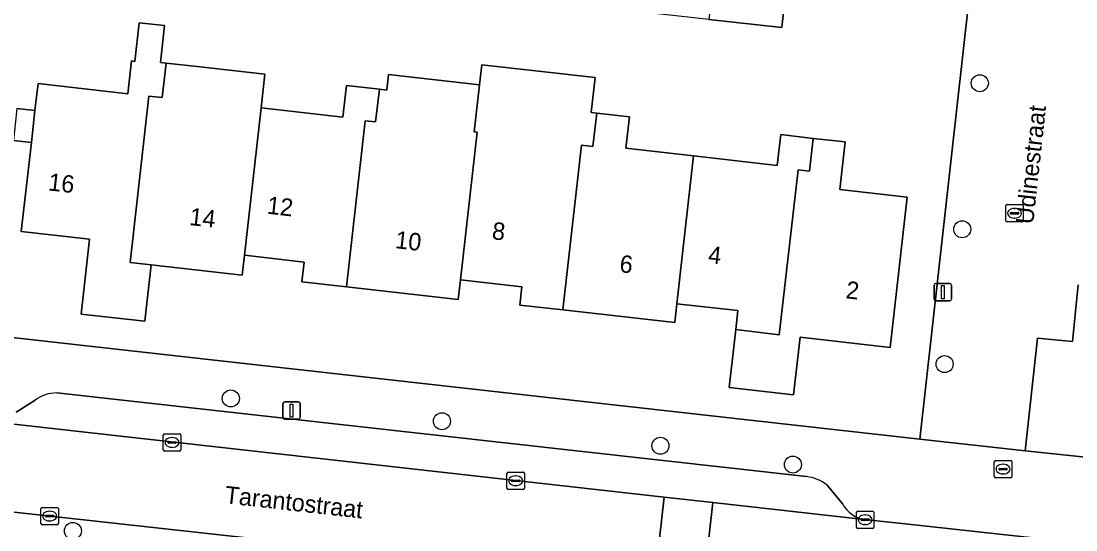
# Model space of a CAD drawing. Extents: x 162082 to 163401, y 388089 to 388636.
# Drawn here: x 162786.3 to 162846.8, y 388208.4 to 388237.6 of the extents above; entities that cross this region are included whole.
import ezdxf

# ---------------------------------------------------------------- set-up
doc = ezdxf.new("R2010")
doc.units = 0
for name, color, linetype in [('IMGEO_Boom', 7, 'Continuous'), ('IMGEO_Brandkraan', 7, 'Continuous'), ('IMGEO_Erf', 7, 'Continuous'), ('IMGEO_Kolk', 7, 'Continuous'), ('IMGEO_Lichtmast', 7, 'Continuous'), ('IMGEO_Openbare_ruimte_label', 7, 'Continuous'), ('IMGEO_Pand', 7, 'Continuous'), ('IMGEO_Pand_nummerreeks', 7, 'Continuous'), ('IMGEO_Parkeervlak_open', 7, 'Continuous'), ('IMGEO_Rijbaan_lokaal_open', 7, 'Continuous'), ('IMGEO_Voetpad_open', 7, 'Continuous')]:
    doc.layers.add(name, color=color, linetype=linetype)

msp = doc.modelspace()

# ---------------------------------------------------------------- linework, layer by layer
at = {"layer": 'IMGEO_Boom'}
for centre in [(162841.322, 388234.002), (162840.312, 388225.617), (162839.302, 388217.879), (162798.306, 388215.904), (162810.433, 388214.596), (162822.978, 388213.187), (162830.586, 388212.107), (162789.234, 388208.298)]:
    msp.add_circle(centre, 0.489, dxfattribs=at)
at = {"layer": 'IMGEO_Brandkraan'}
for p, q in [((162842.154, 388211.422), (162842.154, 388212.274)), ((162842.229, 388212.348), (162843.081, 388212.348)), ((162843.155, 388212.274), (162843.155, 388211.422)), ((162842.413, 388211.842), (162842.413, 388211.854)), ((162842.851, 388211.805), (162842.453, 388211.805)), ((162842.456, 388211.891), (162842.854, 388211.891)), ((162842.642, 388212.128), (162842.667, 388212.128)), ((162842.897, 388211.854), (162842.897, 388211.842)), ((162843.081, 388211.348), (162842.229, 388211.348)), ((162842.665, 388211.568), (162842.64, 388211.568))]:
    msp.add_line(p, q, dxfattribs=at)
for points in [[(162842.154, 388211.422), (162842.154, 388212.274)], [(162842.229, 388212.348), (162843.081, 388212.348)], [(162843.155, 388212.274), (162843.155, 388211.422)], [(162843.081, 388211.348), (162842.229, 388211.348)]]:
    msp.add_lwpolyline(points, dxfattribs=at)
for centre, radius, start, end in [((162842.231, 388212.272), 0.0765, 91.55205, 178.44795), ((162842.231, 388212.272), 0.0765, 91.55205, 178.44795), ((162843.079, 388212.272), 0.0765, 1.55205, 88.44795), ((162843.079, 388212.272), 0.0765, 1.55205, 88.44795), ((162842.453, 388211.851), 0.0403, 85.87752, 175.75265), ((162842.45, 388211.841), 0.0366, 178.93798, 274.71019), ((162842.854, 388211.848), 0.043, 264.86636, 352.45326), ((162842.858, 388211.853), 0.0386, 1.73085, 96.63898), ((162842.231, 388211.424), 0.0765, 181.55205, 268.44795), ((162842.231, 388211.424), 0.0765, 181.55205, 268.44795), ((162843.079, 388211.424), 0.0765, 271.55205, 358.44795), ((162843.079, 388211.424), 0.0765, 271.55205, 358.44795)]:
    msp.add_arc(centre, radius, start, end, dxfattribs=at)
for centre, major_axis, ratio, start_param, end_param in [((162842.641, 388211.848), (-0.387, 0.002), 0.722429, 4.712389, 7.853982), ((162842.666, 388211.848), (-0.39, 0.002), 0.717154, 1.570796, 4.712389)]:
    msp.add_ellipse(centre, major_axis=major_axis, ratio=ratio, start_param=start_param, end_param=end_param, dxfattribs=at)
at = {"layer": 'IMGEO_Erf'}
msp.add_lwpolyline([(162821.433, 388238.137), (162821.739, 388240.934), (162818.357, 388241.345), (162818.041, 388238.547), (162813.346, 388239.079), (162808.513, 388239.648), (162808.844, 388242.48), (162805.899, 388242.824), (162805.568, 388239.992), (162800.951, 388240.532), (162796.218, 388241.085), (162796.532, 388243.772), (162786.323, 388244.931), (162783.503, 388219.652), (162837.876, 388213.576), (162840.707, 388238.931), (162830.248, 388240.007), (162829.943, 388237.21), (162825.765, 388237.665)], close=True, dxfattribs=at)
for points in [[(162786.024, 388232.558), (162787.059, 388232.441), (162787.233, 388233.982), (162792.383, 388233.4), (162792.596, 388235.283), (162792.788, 388235.261), (162793.038, 388237.477), (162794.503, 388237.312), (162794.264, 388235.194), (162794.584, 388235.158), (162796.376, 388234.956), (162800.268, 388234.517), (162800.048, 388232.583), (162804.735, 388232.053), (162804.941, 388233.874), (162806.836, 388233.66), (162807.258, 388233.612), (162807.358, 388234.498), (162812.591, 388233.907), (162812.722, 388235.067), (162819.238, 388234.331), (162819.009, 388232.322), (162819.317, 388232.287), (162821.2, 388232.074), (162820.996, 388230.268), (162824.879, 388229.829), (162829.686, 388229.286), (162829.886, 388231.051), (162831.76, 388230.839), (162833.584, 388230.633), (162833.275, 388227.895), (162837.145, 388227.458), (162836.17, 388218.832), (162831.001, 388219.416), (162830.627, 388216.109), (162826.929, 388216.527), (162827.307, 388219.868), (162827.429, 388220.947), (162823.919, 388221.343), (162823.797, 388220.264), (162817.38, 388220.988), (162814.895, 388221.269), (162815.014, 388222.319), (162811.495, 388222.716), (162811.367, 388221.589), (162804.945, 388222.314), (162802.381, 388222.604), (162802.509, 388223.738), (162799.087, 388224.125), (162798.958, 388222.984), (162793.729, 388223.574), (162793.363, 388220.336), (162789.706, 388220.749), (162790.192, 388225.048), (162786.274, 388225.49), (162786.851, 388230.597), (162785.815, 388230.714)], [(162846.974, 388222.431), (162846.648, 388219.169), (162844.643, 388219.359), (162843.932, 388212.902), (162869.062, 388210.255)]]:
    msp.add_lwpolyline(points, dxfattribs=at)
at = {"layer": 'IMGEO_Kolk'}
for p, q in [((162842.813, 388226.112), (162842.813, 388226.964)), ((162842.888, 388227.038), (162843.74, 388227.038)), ((162843.301, 388226.818), (162843.326, 388226.818)), ((162843.814, 388226.964), (162843.814, 388226.112)), ((162843.072, 388226.532), (162843.072, 388226.544)), ((162843.51, 388226.495), (162843.112, 388226.495)), ((162843.115, 388226.581), (162843.513, 388226.581)), ((162843.324, 388226.258), (162843.299, 388226.258)), ((162843.556, 388226.544), (162843.556, 388226.532)), ((162843.74, 388226.038), (162842.888, 388226.038)), ((162794.427, 388212.952), (162794.427, 388213.804)), ((162794.502, 388213.878), (162795.354, 388213.878)), ((162794.915, 388213.658), (162794.94, 388213.658)), ((162795.428, 388213.804), (162795.428, 388212.952)), ((162795.354, 388212.878), (162794.502, 388212.878)), ((162794.686, 388213.372), (162794.686, 388213.384)), ((162795.124, 388213.335), (162794.726, 388213.335)), ((162794.729, 388213.421), (162795.127, 388213.421)), ((162794.938, 388213.098), (162794.913, 388213.098)), ((162795.17, 388213.384), (162795.17, 388213.372)), ((162814.24, 388211.679), (162815.092, 388211.679)), ((162814.165, 388210.753), (162814.165, 388211.605)), ((162814.424, 388211.173), (162814.424, 388211.185)), ((162814.862, 388211.136), (162814.464, 388211.136)), ((162814.467, 388211.222), (162814.865, 388211.222)), ((162814.653, 388211.459), (162814.678, 388211.459)), ((162814.908, 388211.185), (162814.908, 388211.173)), ((162815.166, 388211.605), (162815.166, 388210.753)), ((162815.092, 388210.679), (162814.24, 388210.679)), ((162814.676, 388210.899), (162814.651, 388210.899)), ((162787.401, 388208.726), (162787.401, 388209.578)), ((162787.476, 388209.652), (162788.328, 388209.652)), ((162787.703, 388209.195), (162788.101, 388209.195)), ((162787.889, 388209.432), (162787.914, 388209.432)), ((162788.402, 388209.578), (162788.402, 388208.726)), ((162834.239, 388208.515), (162834.239, 388209.367)), ((162834.314, 388209.441), (162835.166, 388209.441)), ((162834.727, 388209.221), (162834.752, 388209.221)), ((162835.24, 388209.367), (162835.24, 388208.515)), ((162788.328, 388208.652), (162787.476, 388208.652)), ((162787.66, 388209.146), (162787.66, 388209.158)), ((162788.098, 388209.109), (162787.7, 388209.109)), ((162787.912, 388208.872), (162787.887, 388208.872)), ((162788.144, 388209.158), (162788.144, 388209.146)), ((162834.498, 388208.935), (162834.498, 388208.947)), ((162834.936, 388208.898), (162834.538, 388208.898)), ((162834.541, 388208.984), (162834.939, 388208.984)), ((162834.75, 388208.661), (162834.725, 388208.661)), ((162834.982, 388208.947), (162834.982, 388208.935)), ((162835.166, 388208.441), (162834.314, 388208.441))]:
    msp.add_line(p, q, dxfattribs=at)
for points in [[(162842.813, 388226.112), (162842.813, 388226.964)], [(162842.888, 388227.038), (162843.74, 388227.038)], [(162843.814, 388226.964), (162843.814, 388226.112)], [(162843.74, 388226.038), (162842.888, 388226.038)], [(162794.427, 388212.952), (162794.427, 388213.804)], [(162794.502, 388213.878), (162795.354, 388213.878)], [(162795.428, 388213.804), (162795.428, 388212.952)], [(162795.354, 388212.878), (162794.502, 388212.878)], [(162814.24, 388211.679), (162815.092, 388211.679)], [(162814.165, 388210.753), (162814.165, 388211.605)], [(162815.166, 388211.605), (162815.166, 388210.753)], [(162815.092, 388210.679), (162814.24, 388210.679)], [(162787.401, 388208.726), (162787.401, 388209.578)], [(162787.476, 388209.652), (162788.328, 388209.652)], [(162788.402, 388209.578), (162788.402, 388208.726)], [(162834.239, 388208.515), (162834.239, 388209.367)], [(162834.314, 388209.441), (162835.166, 388209.441)], [(162835.24, 388209.367), (162835.24, 388208.515)], [(162788.328, 388208.652), (162787.476, 388208.652)], [(162835.166, 388208.441), (162834.314, 388208.441)]]:
    msp.add_lwpolyline(points, dxfattribs=at)
for centre, radius, start, end in [((162842.89, 388226.962), 0.0765, 91.55205, 178.44795), ((162842.89, 388226.962), 0.0765, 91.55205, 178.44795), ((162843.738, 388226.962), 0.0765, 1.55205, 88.44795), ((162843.738, 388226.962), 0.0765, 1.55205, 88.44795), ((162843.112, 388226.541), 0.0403, 85.87752, 175.75265), ((162843.109, 388226.531), 0.0366, 178.93798, 274.71019), ((162843.513, 388226.538), 0.043, 264.86636, 352.45326), ((162843.517, 388226.543), 0.0386, 1.73085, 96.63898), ((162842.89, 388226.114), 0.0765, 181.55205, 268.44795), ((162842.89, 388226.114), 0.0765, 181.55205, 268.44795), ((162843.738, 388226.114), 0.0765, 271.55205, 358.44795), ((162843.738, 388226.114), 0.0765, 271.55205, 358.44795), ((162794.504, 388213.802), 0.0765, 91.55205, 178.44795), ((162794.504, 388213.802), 0.0765, 91.55205, 178.44795), ((162795.352, 388213.802), 0.0765, 1.55205, 88.44795), ((162795.352, 388213.802), 0.0765, 1.55205, 88.44795), ((162794.504, 388212.954), 0.0765, 181.55205, 268.44795), ((162794.504, 388212.954), 0.0765, 181.55205, 268.44795), ((162794.726, 388213.381), 0.0403, 85.87752, 175.75265), ((162794.723, 388213.371), 0.0366, 178.93798, 274.71019), ((162795.127, 388213.378), 0.043, 264.86636, 352.45326), ((162795.131, 388213.383), 0.0386, 1.73085, 96.63898), ((162795.352, 388212.954), 0.0765, 271.55205, 358.44795), ((162795.352, 388212.954), 0.0765, 271.55205, 358.44795), ((162814.242, 388211.603), 0.0765, 91.55205, 178.44795), ((162814.242, 388211.603), 0.0765, 91.55205, 178.44795), ((162815.09, 388211.603), 0.0765, 1.55205, 88.44795), ((162815.09, 388211.603), 0.0765, 1.55205, 88.44795), ((162814.464, 388211.182), 0.0403, 85.87752, 175.75265), ((162814.461, 388211.172), 0.0366, 178.93798, 274.71019), ((162814.865, 388211.179), 0.043, 264.86636, 352.45326), ((162814.869, 388211.184), 0.0386, 1.73085, 96.63898), ((162814.242, 388210.755), 0.0765, 181.55205, 268.44795), ((162814.242, 388210.755), 0.0765, 181.55205, 268.44795), ((162815.09, 388210.755), 0.0765, 271.55205, 358.44795), ((162815.09, 388210.755), 0.0765, 271.55205, 358.44795), ((162787.478, 388209.576), 0.0765, 91.55205, 178.44795), ((162787.478, 388209.576), 0.0765, 91.55205, 178.44795), ((162787.7, 388209.155), 0.0403, 85.87752, 175.75265), ((162788.105, 388209.157), 0.0386, 1.73085, 96.63898), ((162788.326, 388209.576), 0.0765, 1.55205, 88.44795), ((162788.326, 388209.576), 0.0765, 1.55205, 88.44795), ((162834.316, 388209.365), 0.0765, 91.55205, 178.44795), ((162834.316, 388209.365), 0.0765, 91.55205, 178.44795), ((162835.164, 388209.365), 0.0765, 1.55205, 88.44795), ((162835.164, 388209.365), 0.0765, 1.55205, 88.44795), ((162787.478, 388208.728), 0.0765, 181.55205, 268.44795), ((162787.478, 388208.728), 0.0765, 181.55205, 268.44795), ((162787.697, 388209.145), 0.0366, 178.93798, 274.71019), ((162788.101, 388209.152), 0.043, 264.86636, 352.45326), ((162788.326, 388208.728), 0.0765, 271.55205, 358.44795), ((162788.326, 388208.728), 0.0765, 271.55205, 358.44795), ((162834.538, 388208.944), 0.0403, 85.87752, 175.75265), ((162834.535, 388208.934), 0.0366, 178.93798, 274.71019), ((162834.939, 388208.941), 0.043, 264.86636, 352.45326), ((162834.943, 388208.946), 0.0386, 1.73085, 96.63898), ((162834.316, 388208.517), 0.0765, 181.55205, 268.44795), ((162834.316, 388208.517), 0.0765, 181.55205, 268.44795), ((162835.164, 388208.517), 0.0765, 271.55205, 358.44795), ((162835.164, 388208.517), 0.0765, 271.55205, 358.44795)]:
    msp.add_arc(centre, radius, start, end, dxfattribs=at)
for centre, major_axis, ratio, start_param, end_param in [((162843.3, 388226.538), (-0.387, 0.002), 0.722429, 4.712389, 7.853982), ((162843.325, 388226.538), (-0.39, 0.002), 0.717154, 1.570796, 4.712389), ((162794.914, 388213.378), (-0.387, 0.002), 0.722429, 4.712389, 7.853982), ((162794.939, 388213.378), (-0.39, 0.002), 0.717154, 1.570796, 4.712389), ((162814.652, 388211.179), (-0.387, 0.002), 0.722429, 4.712389, 7.853982), ((162814.677, 388211.179), (-0.39, 0.002), 0.717154, 1.570796, 4.712389), ((162787.888, 388209.152), (-0.387, 0.002), 0.722429, 4.712389, 7.853982), ((162787.913, 388209.152), (-0.39, 0.002), 0.717154, 1.570796, 4.712389), ((162834.726, 388208.941), (-0.387, 0.002), 0.722429, 4.712389, 7.853982), ((162834.751, 388208.941), (-0.39, 0.002), 0.717154, 1.570796, 4.712389)]:
    msp.add_ellipse(centre, major_axis=major_axis, ratio=ratio, start_param=start_param, end_param=end_param, dxfattribs=at)
at = {"layer": 'IMGEO_Lichtmast'}
for p, q in [((162838.699, 388221.607), (162838.699, 388222.407)), ((162838.699, 388222.407), (162838.699, 388221.607)), ((162838.799, 388222.507), (162839.589, 388222.507)), ((162839.589, 388222.507), (162838.799, 388222.507)), ((162839.689, 388222.407), (162839.689, 388221.607)), ((162839.689, 388221.607), (162839.689, 388222.407)), ((162839.589, 388221.507), (162838.799, 388221.507)), ((162838.799, 388221.507), (162839.589, 388221.507)), ((162801.3, 388214.808), (162801.3, 388215.608)), ((162801.3, 388215.608), (162801.3, 388214.808)), ((162801.4, 388215.708), (162802.19, 388215.708)), ((162802.19, 388215.708), (162801.4, 388215.708)), ((162802.29, 388215.608), (162802.29, 388214.808)), ((162802.29, 388214.808), (162802.29, 388215.608)), ((162802.19, 388214.708), (162801.4, 388214.708)), ((162801.4, 388214.708), (162802.19, 388214.708))]:
    msp.add_line(p, q, dxfattribs=at)
for points in [[(162839.119, 388222.382), (162839.269, 388222.382), (162839.269, 388221.632), (162839.119, 388221.632), (162839.119, 388222.382)], [(162801.72, 388215.583), (162801.87, 388215.583), (162801.87, 388214.833), (162801.72, 388214.833), (162801.72, 388215.583)]]:
    msp.add_lwpolyline(points, dxfattribs=at)
for centre, start, end in [((162838.799, 388222.407), 90, 180), ((162838.799, 388222.407), 90, 180), ((162839.589, 388222.407), 0, 90), ((162839.589, 388222.407), 360, 90), ((162838.799, 388221.607), 180, 270), ((162838.799, 388221.607), 180, 270), ((162839.589, 388221.607), 270, 0), ((162839.589, 388221.607), 270, 0), ((162801.4, 388215.608), 90, 180), ((162801.4, 388215.608), 90, 180), ((162802.19, 388215.608), 0, 90), ((162802.19, 388215.608), 360, 90), ((162801.4, 388214.808), 180, 270), ((162801.4, 388214.808), 180, 270), ((162802.19, 388214.808), 270, 0), ((162802.19, 388214.808), 270, 0)]:
    msp.add_arc(centre, 0.1, start, end, dxfattribs=at)
at = {"layer": 'IMGEO_Pand'}
for points in [[(162830.248, 388240.007), (162826.082, 388240.461), (162825.765, 388237.665), (162829.943, 388237.21)], [(162793.6, 388233.262), (162794.359, 388233.176), (162794.584, 388235.158), (162794.264, 388235.194), (162794.503, 388237.312), (162793.038, 388237.477), (162792.788, 388235.261), (162792.596, 388235.283), (162792.383, 388233.4), (162787.233, 388233.982), (162787.059, 388232.441), (162786.851, 388230.597), (162786.274, 388225.49), (162790.192, 388225.048), (162789.706, 388220.749), (162793.363, 388220.336), (162793.729, 388223.574), (162792.517, 388223.711)], [(162800.048, 388232.583), (162800.268, 388234.517), (162796.376, 388234.956), (162794.584, 388235.158), (162794.359, 388233.176), (162793.6, 388233.262), (162792.517, 388223.711), (162793.729, 388223.574), (162798.958, 388222.984), (162799.087, 388224.125)], [(162818.452, 388230.444), (162819.099, 388230.37), (162819.317, 388232.287), (162819.009, 388232.322), (162819.238, 388234.331), (162812.722, 388235.067), (162812.591, 388233.907), (162812.287, 388231.213), (162812.454, 388231.194), (162811.495, 388222.716), (162815.014, 388222.319), (162814.895, 388221.269), (162817.38, 388220.988)], [(162812.454, 388231.194), (162812.287, 388231.213), (162812.591, 388233.907), (162807.358, 388234.498), (162807.258, 388233.612), (162806.836, 388233.66), (162806.623, 388231.786), (162806.026, 388231.854), (162804.945, 388222.314), (162811.367, 388221.589), (162811.495, 388222.716)], [(162804.945, 388222.314), (162806.026, 388231.854), (162806.623, 388231.786), (162806.836, 388233.66), (162804.941, 388233.874), (162804.735, 388232.053), (162800.048, 388232.583), (162799.087, 388224.125), (162802.509, 388223.738), (162802.381, 388222.604)], [(162787.059, 388232.441), (162786.024, 388232.558), (162785.815, 388230.714), (162786.851, 388230.597)], [(162819.317, 388232.287), (162819.099, 388230.37), (162818.452, 388230.444), (162817.38, 388220.988), (162823.797, 388220.264), (162823.919, 388221.343), (162824.879, 388229.829), (162820.996, 388230.268), (162821.2, 388232.074)], [(162824.879, 388229.829), (162823.919, 388221.343), (162827.429, 388220.947), (162827.307, 388219.868), (162829.804, 388219.55), (162830.88, 388229.035), (162831.547, 388228.959), (162831.76, 388230.839), (162829.886, 388231.051), (162829.686, 388229.286)], [(162831.76, 388230.839), (162831.547, 388228.959), (162830.88, 388229.035), (162829.804, 388219.55), (162827.307, 388219.868), (162826.929, 388216.527), (162830.627, 388216.109), (162831.001, 388219.416), (162836.17, 388218.832), (162837.145, 388227.458), (162833.275, 388227.895), (162833.584, 388230.633)]]:
    msp.add_lwpolyline(points, close=True, dxfattribs=at)
at = {"layer": 'IMGEO_Parkeervlak_open'}
for points in [[(162831.364, 388211.416), (162788.305, 388216.218)], [(162787.062, 388215.802), (162785.981, 388215.126)], [(162784.632, 388214.568), (162823.2, 388210.24), (162825.987, 388209.927), (162834.672, 388208.952)], [(162833.447, 388209.83), (162832.549, 388210.917)]]:
    msp.add_lwpolyline(points, dxfattribs=at)
for centre, radius, start, end in [((162788.263, 388214.278), 1.941, 88.76888, 128.23925), ((162831.168, 388209.294), 2.131, 49.60852, 84.71985), ((162835.022, 388210.734), 1.816, 209.85241, 258.88662)]:
    msp.add_arc(centre, radius, start, end, dxfattribs=at)
at = {"layer": 'IMGEO_Rijbaan_lokaal_open'}
msp.add_lwpolyline([(162847.601, 388300.888), (162845.633, 388283.31), (162845.032, 388277.944), (162844.24, 388270.888), (162843.614, 388265.311), (162841.916, 388250), (162841.425, 388245.495), (162841.16, 388243.06), (162840.876, 388240.446), (162840.868, 388240.375), (162840.707, 388238.931), (162837.876, 388213.576), (162843.932, 388212.902), (162844.643, 388219.359), (162846.648, 388219.169), (162846.974, 388222.431)], dxfattribs=at)
for points in [[(162784.632, 388214.568), (162782.28, 388214.832), (162778.534, 388215.253), (162775.49, 388215.519), (162758.442, 388217.51), (162757.897, 388212.563), (162764.696, 388211.8), (162764.85, 388211.826), (162785.514, 388209.412), (162822.64, 388205.309), (162823.2, 388210.24)], [(162825.427, 388205), (162825.987, 388209.927), (162823.2, 388210.24), (162822.64, 388205.309)], [(162851.342, 388202.136), (162864.571, 388200.674), (162869.36, 388200.134), (162873.136, 388199.708), (162883.87, 388198.497), (162884.429, 388203.536), (162873.467, 388204.758), (162869.711, 388205.176), (162868.91, 388205.265), (162843.687, 388207.981), (162837.039, 388208.697), (162834.672, 388208.952), (162825.987, 388209.927), (162825.427, 388205), (162828.977, 388204.608), (162836.753, 388203.749), (162843.421, 388203.012)]]:
    msp.add_lwpolyline(points, close=True, dxfattribs=at)
at = {"layer": 'IMGEO_Voetpad_open'}
for points in [[(162870.554, 388210.092), (162869.062, 388210.255), (162843.932, 388212.902), (162837.876, 388213.576), (162783.503, 388219.652), (162780.519, 388219.969), (162727.336, 388225.893), (162727.328, 388225.872), (162723.268, 388226.21)], [(162788.305, 388216.218), (162831.364, 388211.416)], [(162785.981, 388215.126), (162787.062, 388215.802)], [(162832.549, 388210.917), (162833.447, 388209.83)], [(162834.672, 388208.952), (162837.039, 388208.697), (162843.687, 388207.981), (162868.91, 388205.265), (162869.711, 388205.176), (162869.766, 388205.672), (162873.522, 388205.254), (162873.467, 388204.758), (162884.429, 388203.536), (162887.205, 388203.227), (162897.852, 388201.954), (162899.823, 388201.772), (162900.237, 388206.821), (162895.523, 388207.331), (162873.536, 388209.762), (162870.554, 388210.092)], [(162825.427, 388205), (162822.64, 388205.309), (162785.514, 388209.412)]]:
    msp.add_lwpolyline(points, dxfattribs=at)
for centre, radius, start, end in [((162788.263, 388214.278), 1.941, 88.76888, 128.23925), ((162831.168, 388209.294), 2.131, 49.60852, 84.71985), ((162835.022, 388210.734), 1.816, 209.85241, 258.88662)]:
    msp.add_arc(centre, radius, start, end, dxfattribs=at)

# ---------------------------------------------------------------- texts
at = {"layer": 'IMGEO_Openbare_ruimte_label'}
for s, rotation, p in [('Udinestraat', 83.68512, (162844.381, 388225.876)), ('Tarantostraat', 353.62818, (162797.923, 388209.893))]:
    msp.add_text(s, height=1, rotation=rotation, dxfattribs=at).set_placement(p)
at = {"layer": 'IMGEO_Pand_nummerreeks'}
for s, rotation, p in [('16', 353.56568, (162787.785, 388227.856)), ('12', 353.54773, (162800.348, 388226.518)), ('14', 353.55995, (162795.896, 388225.866)), ('8', 353.56568, (162813.268, 388225.053)), ('10', 353.55422, (162807.711, 388224.538)), ('4', 353.56308, (162825.682, 388223.68)), ('6', 353.55881, (162820.597, 388223.161)), ('2', 353.55399, (162833.592, 388221.659))]:
    msp.add_text(s, height=1, rotation=rotation, dxfattribs=at).set_placement(p)

doc.saveas('drawing.dxf')
